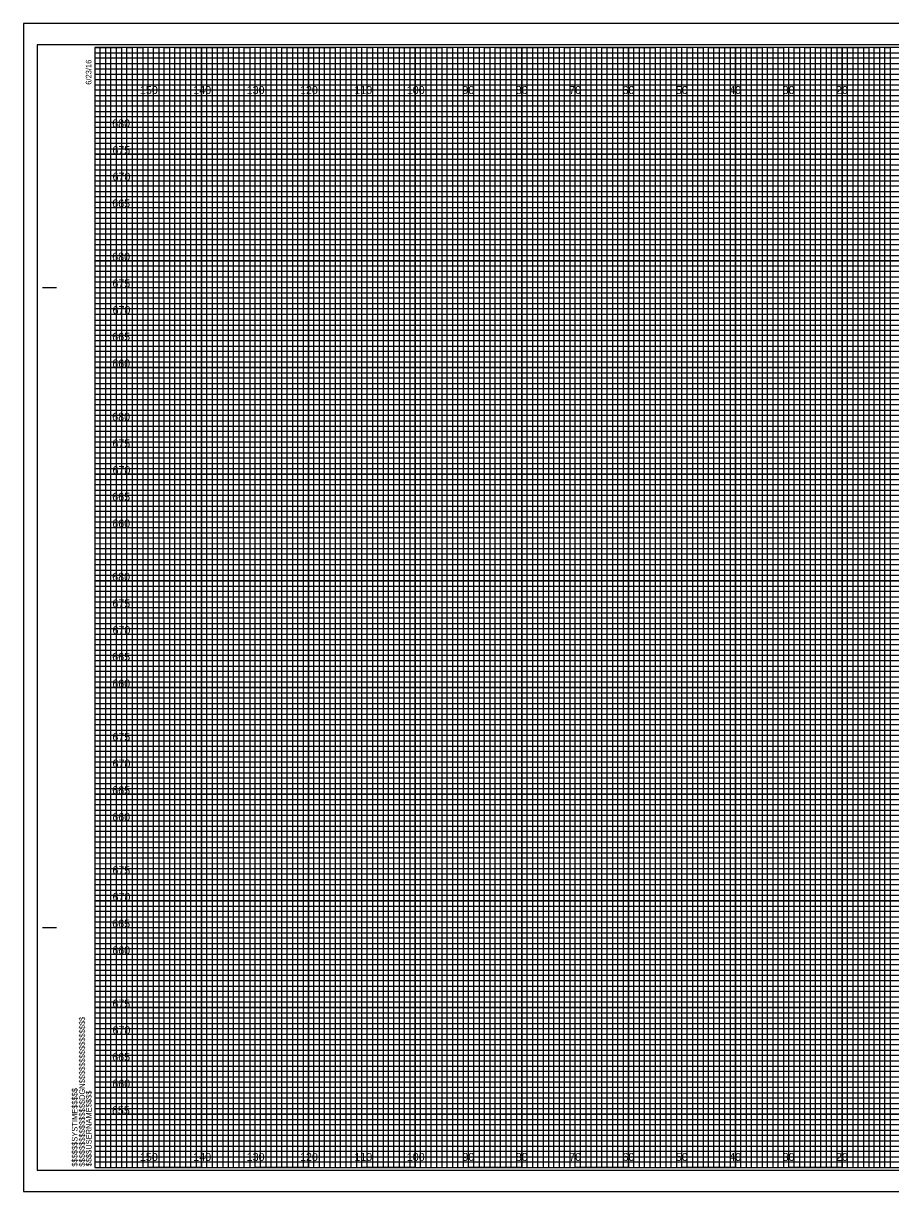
# Model space of a CAD drawing. Extents: x -13 to 323, y 655 to 874.
# Drawn here: x -13.4 to 149.1, y 655.5 to 874.5 of the extents above; entities that cross this region are included whole.
import ezdxf

# ---------------------------------------------------------------- set-up
doc = ezdxf.new("R2010")
doc.units = 0
for name, color, linetype in [('Exist Cross Section Cell', 7, 'Continuous'), ('Exist XS Center Line Elevation Label', 7, 'Continuous'), ('Exist XS Ground Line', 7, 'Continuous'), ('Prop XS Dump Level', 7, 'Continuous'), ('Prop XS Finish Grade', 7, 'Continuous'), ('Prop XS Finish Grade Earthwork', 7, 'Continuous'), ('Prop XS Pvmt Edge Slope', 7, 'Continuous'), ('Prop XS SE Text', 7, 'Continuous'), ('Prop XS Side Slope Text', 7, 'Continuous'), ('Prop XS SS Elevation Text', 7, 'Continuous'), ('Scratch_Level_3', 7, 'Continuous')]:
    doc.layers.add(name, color=color, linetype=linetype)

msp = doc.modelspace()

# ---------------------------------------------------------------- linework, layer by layer
at = {"layer": 'Exist Cross Section Cell'}
for points in [[(0, 870), (5, 870), (5, 660), (15, 660), (15, 870), (25, 870), (25, 660), (35, 660), (35, 870), (45, 870), (45, 660), (55, 660), (55, 870), (65, 870), (65, 660), (75, 660), (75, 870), (85, 870), (85, 660), (95, 660), (95, 870), (105, 870), (105, 660), (115, 660), (115, 870), (125, 870), (125, 660), (135, 660), (135, 870), (145, 870), (145, 660), (155, 660)], [(0, 865), (275, 865)], [(0, 845), (320, 845), (320, 855), (0, 855)], [(0, 825), (320, 825), (320, 835), (0, 835)], [(0, 805), (320, 805), (320, 815), (0, 815)], [(0, 785), (320, 785), (320, 795), (0, 795)], [(0, 765), (320, 765), (320, 775), (0, 775)], [(0, 745), (320, 745), (320, 755), (0, 755)], [(0, 725), (320, 725), (320, 735), (0, 735)], [(0, 705), (320, 705), (320, 715), (0, 715)], [(0, 685), (320, 685), (320, 695), (0, 695)], [(0, 665), (320, 665), (320, 675), (0, 675)]]:
    msp.add_lwpolyline(points, dxfattribs=at)
at = {"layer": 'Exist XS Center Line Elevation Label'}
for p, q in [((10, 870), (0, 870)), ((10, 660), (10, 870)), ((30, 870), (20, 870)), ((20, 870), (20, 660)), ((30, 660), (30, 870)), ((50, 870), (40, 870)), ((40, 870), (40, 660)), ((50, 660), (50, 870)), ((70, 870), (60, 870)), ((60, 870), (60, 660)), ((70, 660), (70, 870)), ((90, 870), (80, 870)), ((80, 870), (80, 660)), ((90, 660), (90, 870)), ((110, 870), (100, 870)), ((100, 870), (100, 660)), ((110, 660), (110, 870)), ((130, 870), (120, 870)), ((120, 870), (120, 660)), ((130, 660), (130, 870)), ((150, 870), (140, 870)), ((140, 870), (140, 660)), ((20, 660), (10, 660)), ((40, 660), (30, 660)), ((60, 660), (50, 660)), ((80, 660), (70, 660)), ((100, 660), (90, 660)), ((120, 660), (110, 660)), ((140, 660), (130, 660))]:
    msp.add_line(p, q, dxfattribs=at)
for points in [[(0, 860), (320, 860), (320, 850), (0, 850)], [(0, 840), (320, 840), (320, 830), (0, 830)], [(0, 820), (320, 820), (320, 810), (0, 810)], [(0, 800), (320, 800), (320, 790), (0, 790)], [(0, 780), (320, 780), (320, 770), (0, 770)], [(0, 760), (320, 760), (320, 750), (0, 750)], [(0, 740), (320, 740), (320, 730), (0, 730)], [(0, 720), (320, 720), (320, 710), (0, 710)], [(0, 700), (320, 700), (320, 690), (0, 690)], [(0, 680), (320, 680), (320, 670), (0, 670)]]:
    msp.add_lwpolyline(points, dxfattribs=at)
at = {"layer": 'Prop XS Dump Level'}
for p, q in [((-9.8, 825), (-7.3, 825)), ((-9.7, 825), (-7.2, 825)), ((-9.8, 705), (-7.3, 705)), ((-9.7, 705), (-7.2, 705)), ((0, 660), (0, 660)), ((0, 660), (0, 660)), ((0, 660), (0, 660)), ((0, 660), (0, 660)), ((0, 660), (0, 660)), ((0, 660), (0, 660)), ((0, 660), (0, 660))]:
    msp.add_line(p, q, dxfattribs=at)
msp.add_lwpolyline([(320, 870), (0, 870), (0, 660), (320, 660)], close=True, dxfattribs=at)
at = {"layer": 'Prop XS Finish Grade Earthwork'}
for p, q in [((10, 660), (10, 870)), ((20, 660), (20, 870)), ((30, 660), (30, 870)), ((40, 660), (40, 870)), ((50, 660), (50, 870)), ((60, 660), (60, 870)), ((70, 660), (70, 870)), ((80, 660), (80, 870)), ((90, 660), (90, 870)), ((100, 660), (100, 870)), ((110, 660), (110, 870)), ((120, 660), (120, 870)), ((130, 660), (130, 870)), ((140, 660), (140, 870)), ((0, 860), (320, 860)), ((0, 850), (320, 850)), ((0, 840), (320, 840)), ((0, 830), (320, 830)), ((0, 820), (320, 820)), ((0, 810), (320, 810)), ((0, 800), (320, 800)), ((0, 790), (320, 790)), ((0, 780), (320, 780)), ((0, 770), (320, 770)), ((0, 760), (320, 760)), ((0, 750), (320, 750)), ((0, 740), (320, 740)), ((0, 730), (320, 730)), ((0, 720), (320, 720)), ((0, 710), (320, 710)), ((0, 700), (320, 700)), ((0, 690), (320, 690)), ((0, 680), (320, 680)), ((0, 670), (320, 670))]:
    msp.add_line(p, q, dxfattribs=at)
at = {"layer": 'Prop XS Pvmt Edge Slope'}
for p, q in [((323.3, 874.5), (-13.4, 874.5)), ((-13.4, 874.5), (-13.4, 655.5)), ((-13.4, 655.5), (323.3, 655.5))]:
    msp.add_line(p, q, dxfattribs=at)
at = {"layer": 'Prop XS SE Text'}
for points in [[(0, 660), (1, 660), (1, 870), (2, 870), (2, 660)], [(2, 660), (3, 660), (3, 870), (4, 870), (4, 660)], [(5, 660), (6, 660), (6, 870), (7, 870), (7, 660)], [(7, 660), (8, 660), (8, 870), (9, 870), (9, 660)], [(10, 660), (11, 660), (11, 870), (12, 870), (12, 660)], [(12, 660), (13, 660), (13, 870), (14, 870), (14, 660)], [(15, 660), (16, 660), (16, 870), (17, 870), (17, 660)], [(17, 660), (18, 660), (18, 870), (19, 870), (19, 660)], [(20, 660), (21, 660), (21, 870), (22, 870), (22, 660)], [(22, 660), (23, 660), (23, 870), (24, 870), (24, 660)], [(25, 660), (26, 660), (26, 870), (27, 870), (27, 660)], [(27, 660), (28, 660), (28, 870), (29, 870), (29, 660)], [(30, 660), (31, 660), (31, 870), (32, 870), (32, 660)], [(32, 660), (33, 660), (33, 870), (34, 870), (34, 660)], [(35, 660), (36, 660), (36, 870), (37, 870), (37, 660)], [(37, 660), (38, 660), (38, 870), (39, 870), (39, 660)], [(40, 660), (41, 660), (41, 870), (42, 870), (42, 660)], [(42, 660), (43, 660), (43, 870), (44, 870), (44, 660)], [(45, 660), (46, 660), (46, 870), (47, 870), (47, 660)], [(47, 660), (48, 660), (48, 870), (49, 870), (49, 660)], [(50, 660), (51, 660), (51, 870), (52, 870), (52, 660)], [(52, 660), (53, 660), (53, 870), (54, 870), (54, 660)], [(55, 660), (56, 660), (56, 870), (57, 870), (57, 660)], [(57, 660), (58, 660), (58, 870), (59, 870), (59, 660)], [(60, 660), (61, 660), (61, 870), (62, 870), (62, 660)], [(62, 660), (63, 660), (63, 870), (64, 870), (64, 660)], [(65, 660), (66, 660), (66, 870), (67, 870), (67, 660)], [(67, 660), (68, 660), (68, 870), (69, 870), (69, 660)], [(70, 660), (71, 660), (71, 870), (72, 870), (72, 660)], [(72, 660), (73, 660), (73, 870), (74, 870), (74, 660)], [(75, 660), (76, 660), (76, 870), (77, 870), (77, 660)], [(77, 660), (78, 660), (78, 870), (79, 870), (79, 660)], [(80, 660), (81, 660), (81, 870), (82, 870), (82, 660)], [(82, 660), (83, 660), (83, 870), (84, 870), (84, 660)], [(85, 660), (86, 660), (86, 870), (87, 870), (87, 660)], [(87, 660), (88, 660), (88, 870), (89, 870), (89, 660)], [(90, 660), (91, 660), (91, 870), (92, 870), (92, 660)], [(92, 660), (93, 660), (93, 870), (94, 870), (94, 660)], [(95, 660), (96, 660), (96, 870), (97, 870), (97, 660)], [(97, 660), (98, 660), (98, 870), (99, 870), (99, 660)], [(100, 660), (101, 660), (101, 870), (102, 870), (102, 660)], [(102, 660), (103, 660), (103, 870), (104, 870), (104, 660)], [(105, 660), (106, 660), (106, 870), (107, 870), (107, 660)], [(107, 660), (108, 660), (108, 870), (109, 870), (109, 660)], [(110, 660), (111, 660), (111, 870), (112, 870), (112, 660)], [(112, 660), (113, 660), (113, 870), (114, 870), (114, 660)], [(115, 660), (116, 660), (116, 870), (117, 870), (117, 660)], [(117, 660), (118, 660), (118, 870), (119, 870), (119, 660)], [(120, 660), (121, 660), (121, 870), (122, 870), (122, 660)], [(122, 660), (123, 660), (123, 870), (124, 870), (124, 660)], [(125, 660), (126, 660), (126, 870), (127, 870), (127, 660)], [(127, 660), (128, 660), (128, 870), (129, 870), (129, 660)], [(130, 660), (131, 660), (131, 870), (132, 870), (132, 660)], [(132, 660), (133, 660), (133, 870), (134, 870), (134, 660)], [(135, 660), (136, 660), (136, 870), (137, 870), (137, 660)], [(137, 660), (138, 660), (138, 870), (139, 870), (139, 660)], [(140, 660), (141, 660), (141, 870), (142, 870), (142, 660)], [(142, 660), (143, 660), (143, 870), (144, 870), (144, 660)], [(145, 660), (146, 660), (146, 870), (147, 870), (147, 660)], [(147, 660), (148, 660), (148, 870), (149, 870), (149, 660)]]:
    msp.add_lwpolyline(points, dxfattribs=at)
at = {"layer": 'Prop XS Side Slope Text'}
msp.add_lwpolyline([(-10.8, 659.5), (322.4, 659.5), (322.4, 870.5), (-10.8, 870.5)], close=True, dxfattribs=at)
at = {"layer": 'Prop XS SS Elevation Text'}
msp.add_lwpolyline([(-13.4, 655.5), (323.3, 655.5), (323.3, 874.5), (-13.4, 874.5)], close=True, dxfattribs=at)
at = {"layer": 'Scratch_Level_3'}
for p, q in [((0, 869), (260, 869)), ((260, 867.98), (0, 867.98)), ((0, 867.98), (0, 867)), ((0, 867), (260, 867)), ((260, 865.89), (0, 865.89)), ((0, 865.89), (0, 864)), ((0, 864), (320, 864))]:
    msp.add_line(p, q, dxfattribs=at)
for points in [[(0, 863), (270, 863), (320, 863), (320, 862), (0, 862)], [(0, 861), (320, 861), (320, 859), (0, 859)], [(0, 858), (320, 858), (320, 857), (0, 856.98)], [(0, 856), (320, 856), (320, 854), (0, 854)], [(0, 853), (320, 853), (320, 852), (0, 852)], [(0, 851), (320, 851), (320, 849), (0, 849)], [(0, 848), (320, 848), (320, 847), (0, 847)], [(0, 846), (320, 846), (320, 844), (0, 844)], [(0, 843), (320, 843), (320, 842), (0, 842)], [(0, 841), (320, 841), (320, 839), (0, 839)], [(0, 838), (320, 838), (320, 837), (0, 837)], [(0, 836), (320, 836), (320, 833.95), (320, 833), (320, 832), (0, 832)], [(0, 834), (320, 834), (320, 833), (0, 833)], [(0, 831), (320, 831), (320, 829), (0, 829.03)], [(0, 829.03), (320, 829), (320, 828), (0, 828)], [(0, 827), (320, 827), (320, 826), (0, 826)], [(0, 824), (320, 824), (320, 823), (0, 823)], [(0, 822), (320, 822), (320, 821), (0, 821)], [(-0.07, 818.89), (320, 818.89), (320, 817.88), (-0.07, 817.88)], [(0, 817), (320, 817), (320, 816), (0, 816)], [(0, 814), (320, 814), (320, 813), (0, 813)], [(0, 812), (320, 812), (320, 811), (0, 811)], [(0, 809), (320, 809), (320, 808), (0, 808)], [(0, 807), (320, 807), (320, 806), (0, 806)], [(0, 804), (320, 804), (320, 803), (0, 803)], [(0, 802), (320, 802), (320, 801), (0, 801)], [(0, 799), (320, 799), (319.99, 797.98), (0, 798)], [(0, 797), (320, 797), (320, 796), (0, 796)], [(0, 794), (320, 794), (320, 793), (0, 793)], [(0, 792), (320, 792), (320, 791), (0, 791)], [(0, 789), (320, 789), (320, 788), (0, 788)], [(0, 787), (320, 787), (320, 786), (0, 786)], [(0, 784), (320, 784), (320, 783), (0, 783)], [(0, 782), (320, 782), (320, 781), (0, 781)], [(0, 779), (320, 779), (320, 778), (0, 778)], [(0, 776.99), (320.07, 776.91), (320, 776), (0, 776)], [(0, 774), (320, 774), (320, 773), (0, 773)], [(0, 772), (320, 772), (320, 771), (0, 771)], [(0, 769), (320, 769), (320, 768), (0, 768)], [(0, 767), (320, 767), (320, 766), (0, 766)], [(0, 764), (320, 764), (320, 763), (0, 763)], [(0, 762), (320, 762), (320, 761), (0, 761)], [(0, 759), (320, 759), (320, 758), (0, 758)], [(0, 757), (320, 757), (320, 756), (0, 756)], [(0, 754), (320, 754), (320, 753), (0, 753)], [(0, 752), (320, 752), (320, 751), (0, 751)], [(0, 749), (320, 749), (320, 748), (0, 748)], [(0, 747), (320, 747), (320, 746), (0, 746)], [(0, 744), (320, 744), (320, 743), (0, 743)], [(0, 742), (320, 742), (320, 741), (0, 741)], [(0, 739), (320, 739), (319.99, 737.98), (0, 738)], [(0, 737), (320, 737), (320, 736), (0, 736)], [(0, 734), (320, 734), (320, 733), (0, 733)], [(0, 732), (320, 732), (320, 731), (0, 731)], [(0, 729), (320, 729), (320, 728), (0, 728)], [(0, 727), (320, 727), (320, 726), (0, 726)], [(0, 724), (320, 724), (320, 723), (0, 723)], [(0, 722), (320, 722), (320, 721), (0, 721)], [(0, 719), (320, 719), (320, 718), (0, 718)], [(0, 716.99), (320.07, 716.91), (320, 716), (0, 716)], [(0, 714), (320, 714), (320, 713), (0, 713)], [(0, 712), (320, 712), (320, 711), (0, 711)], [(0, 709), (320, 709), (320, 708), (0, 708)], [(0, 707), (320, 707), (320, 706), (0, 706)], [(0, 704), (320, 704), (320, 703), (0, 703)], [(0, 702), (320, 702), (320, 701), (0, 701)], [(0, 699), (320, 699), (320, 698), (0, 698)], [(0, 697), (320, 697), (320, 696), (0, 696)], [(0, 694), (320, 694), (320, 693), (0, 693)], [(0, 692), (320, 692), (320, 691), (0, 691)], [(0, 689), (320, 689), (320, 688), (0, 688)], [(0, 687), (320, 687), (320, 686), (0, 686)], [(0, 684), (320, 684), (320, 683), (0, 683)], [(0, 682), (320, 682), (320, 681), (0, 681)], [(0, 679), (320, 679), (320, 678), (0, 678)], [(0, 677), (320, 677), (320, 676), (0, 676)], [(0, 674), (320, 674), (320, 673), (0, 673)], [(0, 672), (320, 672), (320, 671), (0, 671)], [(0, 669), (320, 669), (320, 668), (0, 668)], [(0, 667), (320, 667), (320, 666), (0, 666)], [(0, 664), (320, 664), (320, 663), (0, 663)], [(0, 662), (320, 662), (320, 661), (0, 661)]]:
    msp.add_lwpolyline(points, dxfattribs=at)

# ---------------------------------------------------------------- texts
at = {"layer": 'Exist XS Ground Line'}
for s, p in [('150', (8.44, 861.25)), ('140', (18.44, 861.25)), ('130', (28.44, 861.25)), ('120', (38.44, 861.25)), ('110', (48.62, 861.25)), ('100', (58.44, 861.25)), ('90', (68.86, 861.25)), ('80', (78.86, 861.25)), ('70', (88.86, 861.25)), ('60', (98.86, 861.25)), ('50', (108.86, 861.25)), ('40', (118.86, 861.25)), ('30', (128.86, 861.25)), ('20', (138.86, 861.25)), ('150', (8.44, 661.25)), ('140', (18.44, 661.25)), ('130', (28.44, 661.25)), ('120', (38.44, 661.25)), ('110', (48.62, 661.25)), ('100', (58.44, 661.25)), ('90', (68.86, 661.25)), ('80', (78.86, 661.25)), ('70', (88.86, 661.25)), ('60', (98.86, 661.25)), ('50', (108.86, 661.25)), ('40', (118.86, 661.25)), ('30', (128.86, 661.25)), ('20', (138.86, 661.25))]:
    msp.add_text(s, height=1.5, dxfattribs=at).set_placement(p)
at = {"layer": 'Prop XS Dump Level'}
for s, p in [('6/23/16', (-0.65, 863)), ('$$$$$$$$$$$$$$$$DGN$$$$$$$$$$$$$$$$', (-1.88, 660.18)), ('$$$$$$SYSTIME$$$$$', (-3.26, 660.18)), ('$$$$USERNAME$$$$', (-0.62, 660.23))]:
    msp.add_text(s, height=1.05, rotation=90, dxfattribs=at).set_placement(p)
at = {"layer": 'Prop XS Finish Grade'}
for s, p in [('680', (3.24, 855)), ('675', (3.28, 850)), ('670', (3.3, 845)), ('665', (3.25, 840)), ('680', (3.24, 830)), ('675', (3.28, 825)), ('670', (3.3, 820)), ('665', (3.25, 815)), ('660', (3.26, 810)), ('680', (3.24, 800)), ('675', (3.28, 795)), ('670', (3.3, 790)), ('665', (3.25, 785)), ('660', (3.26, 780)), ('680', (3.24, 770)), ('675', (3.28, 765)), ('670', (3.3, 760)), ('665', (3.25, 755)), ('660', (3.26, 750)), ('675', (3.28, 740)), ('670', (3.3, 735)), ('665', (3.25, 730)), ('660', (3.26, 725)), ('675', (3.28, 715)), ('670', (3.3, 710)), ('665', (3.25, 705)), ('660', (3.26, 700)), ('675', (3.28, 690)), ('670', (3.3, 685)), ('665', (3.25, 680)), ('660', (3.26, 675)), ('655', (3.2, 670))]:
    msp.add_text(s, height=1.5, dxfattribs=at).set_placement(p)

doc.saveas('drawing.dxf')
